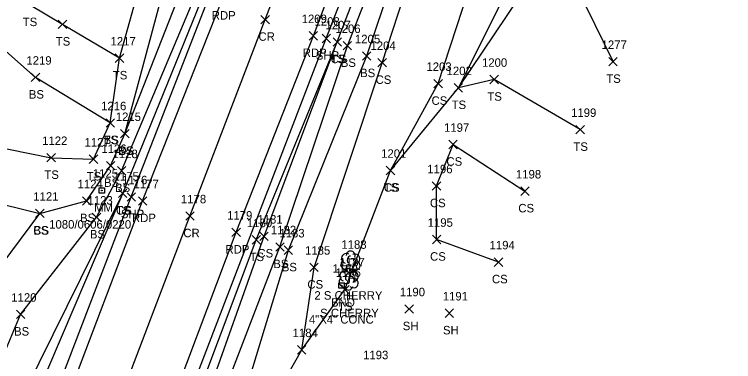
# Model space of a CAD drawing. Extents: x 1554917 to 1555870, y 813367 to 816333.
# Drawn here: x 1555023.3 to 1555192.9, y 813586.9 to 813668.8 of the extents above; entities that cross this region are included whole.
import ezdxf

# ---------------------------------------------------------------- set-up
doc = ezdxf.new("R2010")
doc.units = 0
for name, color, linetype in [('L_A', 7, 'Continuous'), ('L_C', 7, 'Continuous'), ('L_I', 7, 'Continuous'), ('L_TIC', 7, 'Continuous'), ('LELB', 7, 'Continuous'), ('Level 18', 7, 'Continuous'), ('LTD', 7, 'Continuous'), ('M_A', 7, 'Continuous'), ('M_C', 7, 'Continuous'), ('M_I', 7, 'Continuous'), ('P_A', 7, 'Continuous'), ('P_I', 7, 'Continuous'), ('P_TIC', 7, 'Continuous'), ('PET', 7, 'Continuous'), ('PRC', 7, 'Continuous'), ('PSP', 7, 'Continuous'), ('S_A', 7, 'Continuous'), ('S_C', 7, 'Continuous'), ('S_I', 7, 'Continuous'), ('SRM', 7, 'Continuous')]:
    doc.layers.add(name, color=color, linetype=linetype)

msp = doc.modelspace()

# ---------------------------------------------------------------- linework, layer by layer
at = {"layer": 'L_TIC'}
for points in [[(1555033.63, 813665.39), (1555035.63, 813667.39)], [(1555035.63, 813665.39), (1555033.63, 813667.39)], [(1555098.41, 813661.25), (1555100.41, 813663.25)], [(1555100.41, 813661.25), (1555098.41, 813663.25)], [(1555098.41, 813661.25), (1555100.41, 813663.25)], [(1555100.41, 813661.25), (1555098.41, 813663.25)], [(1555100.8, 813660.36), (1555102.8, 813662.36)], [(1555102.8, 813660.36), (1555100.8, 813662.36)], [(1555105.35, 813657.95), (1555107.35, 813659.95)], [(1555107.35, 813657.95), (1555105.35, 813659.95)], [(1555047.09, 813657.42), (1555049.09, 813659.42)], [(1555049.09, 813657.42), (1555047.09, 813659.42)], [(1555047.09, 813657.42), (1555049.09, 813659.42)], [(1555049.09, 813657.42), (1555047.09, 813659.42)], [(1555109.01, 813656.36), (1555111.01, 813658.36)], [(1555111.01, 813656.36), (1555109.01, 813658.36)], [(1555163.42, 813656.6), (1555165.42, 813658.6)], [(1555165.42, 813656.6), (1555163.42, 813658.6)], [(1555027.26, 813652.89), (1555029.26, 813654.89)], [(1555029.26, 813652.89), (1555027.26, 813654.89)], [(1555122.2, 813651.42), (1555124.2, 813653.42)], [(1555124.2, 813651.42), (1555122.2, 813653.42)], [(1555135.39, 813652.39), (1555137.39, 813654.39)], [(1555137.39, 813652.39), (1555135.39, 813654.39)], [(1555126.97, 813650.43), (1555128.97, 813652.43)], [(1555128.97, 813650.43), (1555126.97, 813652.43)], [(1555126.97, 813650.43), (1555128.97, 813652.43)], [(1555128.97, 813650.43), (1555126.97, 813652.43)], [(1555044.91, 813642.15), (1555046.91, 813644.15)], [(1555046.91, 813642.15), (1555044.91, 813644.15)], [(1555044.91, 813642.15), (1555046.91, 813644.15)], [(1555046.91, 813642.15), (1555044.91, 813644.15)], [(1555048.32, 813639.6), (1555050.32, 813641.6)], [(1555050.32, 813639.6), (1555048.32, 813641.6)], [(1555048.32, 813639.6), (1555050.32, 813641.6)], [(1555050.32, 813639.6), (1555048.32, 813641.6)], [(1555155.68, 813640.57), (1555157.68, 813642.57)], [(1555157.68, 813640.57), (1555155.68, 813642.57)], [(1555125.71, 813637.06), (1555127.71, 813639.06)], [(1555127.71, 813637.06), (1555125.71, 813639.06)], [(1555030.95, 813633.95), (1555032.95, 813635.95)], [(1555032.95, 813633.95), (1555030.95, 813635.95)], [(1555040.94, 813633.59), (1555042.94, 813635.59)], [(1555042.94, 813633.59), (1555040.94, 813635.59)], [(1555044.98, 813632.07), (1555046.98, 813634.07)], [(1555046.98, 813632.07), (1555044.98, 813634.07)], [(1555047.58, 813630.85), (1555049.58, 813632.85)], [(1555049.58, 813630.85), (1555047.58, 813632.85)], [(1555110.95, 813630.93), (1555112.95, 813632.93)], [(1555112.95, 813630.93), (1555110.95, 813632.93)], [(1555110.95, 813630.93), (1555112.95, 813632.93)], [(1555112.95, 813630.93), (1555110.95, 813632.93)], [(1555121.82, 813627.28), (1555123.82, 813629.28)], [(1555123.82, 813627.28), (1555121.82, 813629.28)], [(1555047.82, 813625.54), (1555049.82, 813627.54)], [(1555049.82, 813625.54), (1555047.82, 813627.54)], [(1555047.82, 813625.54), (1555049.82, 813627.54)], [(1555049.82, 813625.54), (1555047.82, 813627.54)], [(1555142.66, 813626.05), (1555144.66, 813628.05)], [(1555144.66, 813626.05), (1555142.66, 813628.05)], [(1555039.32, 813623.75), (1555041.32, 813625.75)], [(1555041.32, 813623.75), (1555039.32, 813625.75)], [(1555028.3, 813620.81), (1555030.3, 813622.81)], [(1555030.3, 813620.81), (1555028.3, 813622.81)], [(1555028.3, 813620.81), (1555030.3, 813622.81)], [(1555030.3, 813620.81), (1555028.3, 813622.81)], [(1555041.65, 813619.9), (1555043.65, 813621.9)], [(1555043.65, 813619.9), (1555041.65, 813621.9)], [(1555081.14, 813615.42), (1555083.14, 813617.42)], [(1555083.14, 813615.42), (1555081.14, 813617.42)], [(1555079.33, 813614.57), (1555081.33, 813616.57)], [(1555081.33, 813614.57), (1555079.33, 813616.57)], [(1555121.84, 813614.66), (1555123.84, 813616.66)], [(1555123.84, 813614.66), (1555121.84, 813616.66)], [(1555084.89, 813612.91), (1555086.89, 813614.91)], [(1555086.89, 813612.91), (1555084.89, 813614.91)], [(1555086.88, 813612.15), (1555088.88, 813614.15)], [(1555088.88, 813612.15), (1555086.88, 813614.15)], [(1555136.44, 813609.33), (1555138.44, 813611.33)], [(1555138.44, 813609.33), (1555136.44, 813611.33)], [(1555092.93, 813608.08), (1555094.93, 813610.08)], [(1555094.93, 813608.08), (1555092.93, 813610.08)], [(1555100.22, 813602.84), (1555102.22, 813604.84)], [(1555102.22, 813602.84), (1555100.22, 813604.84)], [(1555100.22, 813602.84), (1555102.22, 813604.84)], [(1555102.22, 813602.84), (1555100.22, 813604.84)], [(1555023.77, 813596.99), (1555025.77, 813598.99)], [(1555025.77, 813596.99), (1555023.77, 813598.99)], [(1555115.37, 813598.27), (1555117.37, 813600.27)], [(1555117.37, 813598.27), (1555115.37, 813600.27)], [(1555124.84, 813597.28), (1555126.84, 813599.28)], [(1555126.84, 813597.28), (1555124.84, 813599.28)], [(1555090.02, 813588.64), (1555092.02, 813590.64)], [(1555092.02, 813588.64), (1555090.02, 813590.64)], [(1555090.02, 813588.64), (1555092.02, 813590.64)], [(1555092.02, 813588.64), (1555090.02, 813590.64)]]:
    msp.add_lwpolyline(points, dxfattribs=at)
at = {"layer": 'LELB'}
for points in [[(1555019.54, 813585.69), (1555024.77, 813597.99), (1555042.65, 813620.9), (1555048.58, 813631.85), (1555066.52, 813674.6), (1555093.66, 813750.68), (1555103.98, 813778.92), (1555100.94, 813788.26), (1555095.86, 813797.4), (1555100.34, 813804.26), (1555113.07, 813834.65), (1555120.88, 813859.4), (1555126.12, 813877.4), (1555144.96, 813909.35), (1555149.61, 813919.5), (1555153.95, 813930.09), (1555158.29, 813940)], [(1554960.86, 813387.22), (1554975.88, 813430.61), (1554997.67, 813492.71), (1555013.89, 813538.05), (1555028.68, 813579.18), (1555048.82, 813626.54), (1555068.18, 813674.18), (1555096.05, 813749.22), (1555111.01, 813785.1), (1555115.51, 813798.83), (1555119.3, 813812.87), (1555134.87, 813853.17), (1555141.95, 813870.8), (1555155.34, 813907.69), (1555153.32, 813917.67), (1555161.57, 813925.65), (1555168.92, 813938.89)], [(1555101.22, 813603.84), (1555111.95, 813631.93), (1555127.97, 813651.43), (1555152.02, 813699.54), (1555162.91, 813721.01), (1555173.86, 813750.23), (1555186.14, 813780.13), (1555202.44, 813820.35), (1555215.18, 813875.95), (1555215.28, 813897.96), (1555212.9, 813910.7), (1555212.19, 813917.21), (1555210.66, 813920.37), (1555207.16, 813922.92), (1555203.03, 813922.76), (1555199.5, 813919.6)], [(1554992.4, 813377.01), (1555009.62, 813423.34), (1555030.72, 813482.86), (1555047.7, 813528.1), (1555056, 813550.42), (1555062.05, 813566.99), (1555080.33, 813615.57), (1555099.41, 813662.25), (1555114.13, 813700.62), (1555127, 813733.84), (1555152.94, 813799.24), (1555168.16, 813840.25), (1555187.47, 813890.8), (1555199.5, 813919.6)], [(1555091.02, 813589.64), (1555093.93, 813609.08), (1555110.01, 813657.36), (1555123.68, 813699.33), (1555136.3, 813730.66), (1555163.02, 813794.74), (1555179.29, 813835.95), (1555197.25, 813886.69), (1555209.44, 813915.13), (1555210.66, 813920.37)], [(1554997.34, 813375.96), (1555001.03, 813380.2), (1555008.26, 813399.3), (1555016.85, 813422.36), (1555039.01, 813478.41), (1555055.21, 813525.71), (1555062.73, 813548.53), (1555066.84, 813564.4), (1555085.89, 813613.91), (1555101.8, 813661.36), (1555117.2, 813700.9), (1555129.69, 813732.82), (1555155.55, 813797.61), (1555171.4, 813838.65), (1555190.74, 813889.78), (1555201.42, 813914.42), (1555204.39, 813917.83), (1555206.44, 813916.94)], [(1555060.32, 813524.58), (1555067.83, 813537.87), (1555070.43, 813550.96), (1555072.05, 813560.86), (1555087.88, 813613.15), (1555106.35, 813658.95), (1555120.2, 813700.04), (1555133.19, 813731.1), (1555158.65, 813797.07), (1555174.38, 813837.99), (1555194.21, 813888.82), (1555206.44, 813916.94)], [(1555111.95, 813631.93), (1555123.2, 813652.42), (1555137.56, 813696.49), (1555156.74, 813743.02), (1555177.49, 813784.47), (1555191.84, 813829.42), (1555205.71, 813882.43), (1555212.9, 813910.7)], [(1554949.33, 813611.76), (1554977.21, 813618.67), (1554998.22, 813624.91), (1555016.24, 813625.01), (1555029.3, 813621.81), (1555040.32, 813624.75), (1555045.98, 813633.07), (1555049.32, 813640.6), (1555063.34, 813676.25), (1555081.89, 813724.28), (1555091.18, 813752.08), (1555095.69, 813774.96), (1555088.32, 813786.78), (1555082.82, 813809.08), (1555086.32, 813807.6), (1555081.46, 813811.86)], [(1554954.51, 813629.31), (1554971.74, 813631.07), (1554998.18, 813639.71), (1555016.83, 813638), (1555031.95, 813634.95), (1555041.94, 813634.59), (1555045.91, 813643.15), (1555048.09, 813658.42), (1555054.81, 813682.71), (1555073.55, 813727.86), (1555077.68, 813738.56), (1555087.17, 813753.94), (1555095.69, 813774.96)], [(1555045.91, 813643.15), (1555028.26, 813653.89), (1555014.84, 813665.72), (1555013.69, 813690.7), (1555025.72, 813719.45), (1555039.73, 813739.79), (1555060.31, 813748.49), (1555087.17, 813753.94)], [(1555049.32, 813640.6), (1555059.57, 813678.69), (1555078.61, 813726.66), (1555091.18, 813752.08)], [(1555048.09, 813658.42), (1555034.63, 813666.39), (1555026.85, 813670.99), (1555028.13, 813688.37), (1555037.39, 813715.28), (1555045.69, 813723.46), (1555063.18, 813725.38), (1555077.68, 813738.56)], [(1555156.68, 813641.57), (1555136.39, 813653.39), (1555127.97, 813651.43), (1555159.54, 813698.33), (1555155.8, 813675.23), (1555164.42, 813657.6)], [(1554994.08, 813375.71), (1555012.26, 813423.24), (1555033.65, 813482.08), (1555051.39, 813527.17), (1555057.7, 813549.3), (1555064.2, 813565.75), (1555082.14, 813616.42), (1555099.41, 813662.25)], [(1555137.44, 813610.33), (1555122.84, 813615.66), (1555122.82, 813628.28), (1555126.71, 813638.06), (1555143.66, 813627.05)], [(1554955.97, 813389.51), (1554961.01, 813406.77), (1554970.65, 813432.6), (1554989.8, 813496.28), (1555007.9, 813540.38), (1555025.82, 813579.85), (1555048.82, 813626.54)], [(1554928.52, 813569.72), (1554947.56, 813564.37), (1554964.46, 813556.66), (1554984.28, 813565), (1554997.17, 813568.08), (1555012.26, 813566.6), (1555009.99, 813588.02), (1555015.55, 813603.36), (1555029.3, 813621.81)], [(1555104.83, 813563.19), (1555089.64, 813565.56), (1555077.66, 813559.05), (1555084.43, 813577.98), (1555091.02, 813589.64), (1555101.22, 813603.84)]]:
    msp.add_lwpolyline(points, dxfattribs=at)
at = {"layer": 'Level 18'}
msp.add_lwpolyline([(1555099.81, 813605.45), (1555101.06, 813605.45), (1555101.06, 813604.2), (1555099.81, 813604.2)], close=True, dxfattribs=at)
msp.add_circle((1555100.44, 813604.82), 0.0833, dxfattribs=at)
at = {"layer": 'LTD'}
for p, q in [((1555102.51, 813610.47), (1555102.51, 813610.47)), ((1555102.51, 813610.47), (1555102.51, 813610.47)), ((1555102.07, 813606.33), (1555102.07, 813606.33)), ((1555102.07, 813606.33), (1555102.07, 813606.33))]:
    msp.add_line(p, q, dxfattribs=at)
for centre in [(1555102.56, 813611.9), (1555102.12, 813607.76)]:
    msp.add_arc(centre, 1.05, 335.5272, 180.9563, dxfattribs=at)
for centre, major_axis, ratio, start_param, end_param in [((1555101.72, 813611.14), (1.21, -0.51), 0.895232, 1.570796, 4.712389), ((1555103.55, 813611.05), (-1.14, -0.48), 0.949671, 1.570796, 4.712389), ((1555101.43, 813609.76), (0.58, -1.04), 0.959034, 3.141593, 6.283185), ((1555102.3, 813610.93), (-0.208, -0.792), 0.645439, 3.141593, 6.283185), ((1555103.01, 813610.3), (-0.5, 0.667), 0.989748, 3.141593, 6.283185), ((1555103.51, 813609.64), (-1.09, 0.79), 0.841452, 1.570796, 4.712389), ((1555102.51, 813608.97), (0.26, 1.06), 0.942809, 1.570796, 4.712389), ((1555102.05, 813609.72), (-0.625, -0.083), 0.423636, 0, 3.141593), ((1555101.28, 813607), (1.21, -0.51), 0.895232, 1.570796, 4.712389), ((1555101.87, 813606.79), (-0.208, -0.792), 0.645439, 3.141593, 6.283185), ((1555103.12, 813606.91), (-1.14, -0.48), 0.949671, 1.570796, 4.712389), ((1555100.99, 813605.62), (0.58, -1.04), 0.959034, 3.141593, 6.283185), ((1555101.62, 813605.58), (-0.625, -0.083), 0.423636, 0, 3.141593), ((1555102.57, 813606.16), (-0.5, 0.667), 0.989748, 3.141593, 6.283185), ((1555103.07, 813605.5), (-1.09, 0.79), 0.841452, 1.570796, 4.712389), ((1555102.07, 813604.83), (0.26, 1.06), 0.942809, 1.570796, 4.712389)]:
    msp.add_ellipse(centre, major_axis=major_axis, ratio=ratio, start_param=start_param, end_param=end_param, dxfattribs=at)
at = {"layer": 'P_TIC'}
for points in [[(1555081.41, 813666.53), (1555083.41, 813668.53)], [(1555083.41, 813666.53), (1555081.41, 813668.53)], [(1555092.79, 813662.7), (1555094.79, 813664.7)], [(1555094.79, 813662.7), (1555092.79, 813664.7)], [(1555095.82, 813662.08), (1555097.82, 813664.08)], [(1555097.82, 813662.08), (1555095.82, 813664.08)], [(1555049.86, 813624.69), (1555051.86, 813626.69)], [(1555051.86, 813624.69), (1555049.86, 813626.69)], [(1555052.52, 813623.76), (1555054.52, 813625.76)], [(1555054.52, 813623.76), (1555052.52, 813625.76)], [(1555063.69, 813620.19), (1555065.69, 813622.19)], [(1555065.69, 813620.19), (1555063.69, 813622.19)], [(1555074.57, 813616.35), (1555076.57, 813618.35)], [(1555076.57, 813616.35), (1555074.57, 813618.35)]]:
    msp.add_lwpolyline(points, dxfattribs=at)
at = {"layer": 'PET'}
for points in [[(1554965.43, 813385.56), (1554980.95, 813429.92), (1555003.19, 813490.59), (1555019.55, 813535.73), (1555035.2, 813576.47), (1555053.52, 813624.76), (1555072.33, 813672.52), (1555101.11, 813747.71), (1555125.53, 813809.89), (1555141.72, 813851.12), (1555161.36, 813900.53), (1555183.5, 813956.99)], [(1554987.55, 813378.28), (1555004.34, 813425.43), (1555025.15, 813482.53), (1555042.33, 813529.78), (1555057.09, 813568.35), (1555075.57, 813617.35), (1555093.79, 813663.7), (1555108.49, 813702.81), (1555121.71, 813736.27), (1555147.41, 813801.52), (1555163.02, 813841.94), (1555182.57, 813892.25), (1555203.7, 813945.01)]]:
    msp.add_lwpolyline(points, dxfattribs=at)
at = {"layer": 'PRC'}
msp.add_lwpolyline([(1554976.76, 813382.18), (1554992.84, 813427.9), (1555014.07, 813486.01), (1555030.62, 813532.31), (1555046.37, 813573.08), (1555064.69, 813621.19), (1555082.41, 813667.53), (1555112.1, 813744.1), (1555110.69, 813739.79), (1555136.16, 813805.74), (1555152.52, 813846.93), (1555172.03, 813896.18), (1555193.96, 813951.2), (1555206.37, 813983.4), (1555218.13, 814013.22), (1555228.65, 814039.26), (1555237.93, 814064.31), (1555252.22, 814099.76), (1555265.8, 814135.89), (1555275.26, 814160.09), (1555297.17, 814214.77), (1555313.83, 814257.94), (1555329.72, 814298.26), (1555342.03, 814329.92)], dxfattribs=at)
at = {"layer": 'PSP'}
for points in [[(1554990.52, 813377.71), (1555007.26, 813424.1), (1555027.97, 813481.79), (1555045.41, 813528.93), (1555059.94, 813567), (1555096.82, 813663.08), (1555111.75, 813701.59), (1555124.82, 813734.75), (1555150.26, 813800.36), (1555166.19, 813840.91), (1555185.69, 813891.41), (1555197.67, 813922.42), (1555211.91, 813956.86)], [(1554963, 813386.3), (1554978.53, 813430.4), (1555000.44, 813491.39), (1555017.18, 813537.03), (1555032.55, 813577.93), (1555050.86, 813625.69), (1555069.49, 813673.81), (1555098.21, 813748.28), (1555122.69, 813810.6), (1555138.9, 813851.92), (1555160.79, 813906.47), (1555173.05, 813937.33)]]:
    msp.add_lwpolyline(points, dxfattribs=at)
at = {"layer": 'SRM'}
msp.add_lwpolyline([(1555043.27, 813627.85), (1555044.52, 813627.85), (1555044.52, 813626.6), (1555043.27, 813626.6)], close=True, dxfattribs=at)
msp.add_circle((1555043.89, 813627.23), 0.0833, dxfattribs=at)

# ---------------------------------------------------------------- texts
at = {"layer": 'L_A'}
for s, p in [('TS', (1555025.26, 813665.99)), ('TS', (1555033.04, 813661.39)), ('TS', (1555097.82, 813657.25)), ('CS', (1555097.85, 813657.25)), ('BS', (1555100.24, 813656.36)), ('TS', (1555046.5, 813653.42)), ('TS', (1555046.5, 813653.42)), ('BS', (1555104.79, 813653.95)), ('TS', (1555162.83, 813652.6)), ('CS', (1555108.45, 813652.36)), ('BS', (1555026.7, 813648.89)), ('TS', (1555134.8, 813648.39)), ('CS', (1555121.64, 813647.42)), ('TS', (1555126.37, 813646.43)), ('TS', (1555126.37, 813646.43)), ('TS', (1555044.32, 813638.15)), ('BS', (1555044.35, 813638.15)), ('TS', (1555155.09, 813636.57)), ('CS', (1555047.76, 813635.6)), ('BS', (1555047.76, 813635.6)), ('CS', (1555125.15, 813633.06)), ('TS', (1555030.36, 813629.95)), ('TS', (1555040.35, 813629.59)), ('BS', (1555044.42, 813628.07)), ('BS', (1555047.02, 813626.85)), ('TS', (1555110.36, 813626.93)), ('CS', (1555110.4, 813626.93)), ('CS', (1555121.26, 813623.28)), ('CS', (1555142.1, 813622.05)), ('TS', (1555047.23, 813621.54)), ('CS', (1555047.26, 813621.54)), ('BS', (1555038.77, 813619.75)), ('CS', (1555027.75, 813616.81)), ('BS', (1555027.75, 813616.81)), ('BS', (1555041.1, 813615.9)), ('TS', (1555078.74, 813610.57)), ('CS', (1555080.58, 813611.42)), ('CS', (1555121.29, 813610.66)), ('BS', (1555084.33, 813608.91)), ('BS', (1555086.33, 813608.15)), ('H', (1555101.94, 813605.47)), ('CS', (1555135.88, 813605.33)), ('CS', (1555092.37, 813604.08)), ('H', (1555101.51, 813601.33)), ('TS', (1555099.62, 813598.84)), ('TS', (1555099.62, 813598.84)), ('SH', (1555114.85, 813594.27)), ('SH', (1555124.33, 813593.28)), ('BS', (1555023.21, 813592.99))]:
    msp.add_text(s, height=2, dxfattribs=at).set_placement(p)
at = {"layer": 'L_C'}
for s, p in [('2 S.CHERRY', (1555094.02, 813601.47)), ('S.CHERRY', (1555095.38, 813597.33))]:
    msp.add_text(s, height=2, dxfattribs=at).set_placement(p)
at = {"layer": 'L_I'}
for s, p in [('1207', (1555096.64, 813665.25)), ('1207', (1555096.64, 813665.25)), ('1206', (1555098.97, 813664.36)), ('1217', (1555045.96, 813661.42)), ('1217', (1555045.96, 813661.42)), ('1205', (1555103.58, 813661.95)), ('1204', (1555107.24, 813660.36)), ('1277', (1555161.73, 813660.6)), ('1219', (1555026.12, 813656.89)), ('1200', (1555133.53, 813656.39)), ('1203', (1555120.43, 813655.42)), ('1202', (1555125.19, 813654.43)), ('1202', (1555125.19, 813654.43)), ('1216', (1555043.73, 813646.15)), ('1216', (1555043.73, 813646.15)), ('1199', (1555154.54, 813644.57)), ('1215', (1555047.19, 813643.6)), ('1215', (1555047.19, 813643.6)), ('1197', (1555124.58, 813641.06)), ('1122', (1555029.83, 813637.95)), ('1127', (1555039.82, 813637.59)), ('1126', (1555043.8, 813636.07)), ('1128', (1555046.45, 813634.85)), ('1201', (1555109.75, 813634.93)), ('1201', (1555109.75, 813634.93)), ('1196', (1555120.64, 813631.28)), ('1175', (1555046.69, 813629.54)), ('1175', (1555046.69, 813629.54)), ('1198', (1555141.53, 813630.05)), ('1124', (1555038.2, 813627.75)), ('1121', (1555027.75, 813624.81)), ('1121', (1555027.75, 813624.81)), ('1123', (1555040.53, 813623.9)), ('1181', (1555080.58, 813619.42)), ('1195', (1555120.72, 813618.66)), ('1180', (1555078.12, 813618.57)), ('1182', (1555083.76, 813616.91)), ('1183', (1555085.76, 813616.15)), ('1185', (1555091.81, 813612.08)), ('1188', (1555100.38, 813613.47)), ('1194', (1555135.32, 813613.33)), ('1187', (1555099.95, 813609.33)), ('1186', (1555099.03, 813606.84)), ('1186', (1555099.03, 813606.84)), ('1190', (1555114.15, 813602.27)), ('1120', (1555022.56, 813600.99)), ('1191', (1555124.28, 813601.28)), ('1184', (1555088.89, 813592.64)), ('1184', (1555088.89, 813592.64)), ('1193', (1555105.5, 813587.42))]:
    msp.add_text(s, height=2, dxfattribs=at).set_placement(p)
at = {"layer": 'M_A'}
msp.add_text('BND', height=2, dxfattribs=at).set_placement((1555097.93, 813599.82))
at = {"layer": 'M_C'}
msp.add_text('4"X4" CONC', height=2, dxfattribs=at).set_placement((1555092.73, 813595.82))
at = {"layer": 'M_I'}
msp.add_text('1189', height=2, dxfattribs=at).set_placement((1555098.3, 813607.82))
at = {"layer": 'P_A'}
for s, p in [('RDP', (1555069.82, 813667.52)), ('CR', (1555080.84, 813662.53)), ('RDP', (1555091.28, 813658.7)), ('SHP', (1555094.35, 813658.08)), ('SHP', (1555048.4, 813620.69)), ('RDP', (1555051.01, 813619.76)), ('CR', (1555063.12, 813616.19)), ('RDP', (1555073.06, 813612.35))]:
    msp.add_text(s, height=2, dxfattribs=at).set_placement(p)
at = {"layer": 'P_I'}
for s, p in [('1209', (1555091.02, 813666.7)), ('1208', (1555094.05, 813666.08)), ('1176', (1555048.68, 813628.69)), ('1177', (1555051.39, 813627.76)), ('1178', (1555062.56, 813624.19)), ('1179', (1555073.44, 813620.35))]:
    msp.add_text(s, height=2, dxfattribs=at).set_placement(p)
at = {"layer": 'S_A'}
msp.add_text('MM', height=2, dxfattribs=at).set_placement((1555042.08, 813622.23))
at = {"layer": 'S_C'}
msp.add_text('1080/0606/0220', height=2, dxfattribs=at).set_placement((1555031.49, 813618.23))
at = {"layer": 'S_I'}
msp.add_text('1125', height=2, dxfattribs=at).set_placement((1555041.77, 813630.23))

doc.saveas('drawing.dxf')
